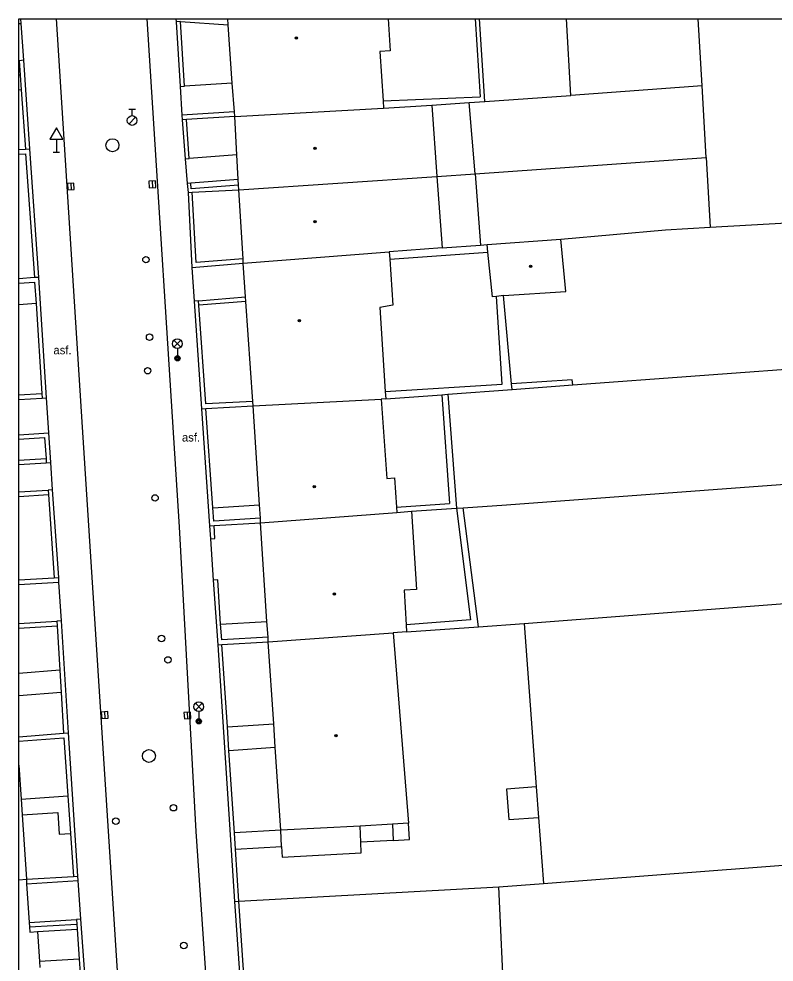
# Model space of a CAD drawing. Extents: x -596024 to -594475, y -1163820 to -1161957.
# Drawn here: x -596024.4 to -595966.1, y -1162029.7 to -1161956.9 of the extents above; entities that cross this region are included whole.
import ezdxf

# ---------------------------------------------------------------- set-up
doc = ezdxf.new("R2010")
doc.units = 0
for name, color, linetype in [('Level 10', 7, 'Continuous'), ('Level 11', 7, 'Continuous'), ('Level 27', 7, 'Continuous'), ('Level 28', 7, 'Continuous'), ('Level 33', 7, 'Continuous'), ('Level 34', 7, 'Continuous'), ('Level 39', 7, 'Continuous'), ('Level 40', 7, 'Continuous'), ('Level 5', 7, 'Continuous'), ('Level 7', 7, 'Continuous'), ('Level 8', 7, 'Continuous'), ('Vrstva 63', 7, 'Continuous')]:
    doc.layers.add(name, color=color, linetype=linetype)

msp = doc.modelspace()

# ---------------------------------------------------------------- linework, layer by layer
at = {"layer": 'Level 10'}
for points in [[(-596021.533, -1161956.88), (-596019.52, -1161988.41), (-596013.74, -1162078.43)], [(-596014.537, -1161956.88), (-596012.03, -1161996.13), (-596010.74, -1162019.65), (-596006.59, -1162080.3)]]:
    msp.add_lwpolyline(points, dxfattribs=at)
at = {"layer": 'Level 11'}
for p, q in [((-596024.42, -1161956.904), (-596024.26, -1161956.89)), ((-595989.166, -1161956.88), (-595988.78, -1161962.9)), ((-595988.41, -1161963.27), (-595988.833, -1161956.88)), ((-595981.78, -1161962.79), (-595982.099, -1161956.88)), ((-595971.64, -1161962.05), (-595971.936, -1161956.88)), ((-596024.31, -1161961.22), (-596024.42, -1161961.227)), ((-596024.23, -1161962.37), (-596024.42, -1161962.383)), ((-596023.09, -1161978.88), (-596024.42, -1161978.965)), ((-596024.42, -1161985.925), (-596022.65, -1161985.82)), ((-596024.42, -1161986.279), (-596022.63, -1161986.17)), ((-596024.42, -1161990.958), (-596022.32, -1161990.83)), ((-596024.42, -1161991.31), (-596022.3, -1161991.18)), ((-596024.42, -1161993.424), (-596022.15, -1161993.28)), ((-596024.42, -1161993.775), (-596022.13, -1161993.63)), ((-596024.42, -1162003.587), (-596021.48, -1162003.41)), ((-596024.42, -1162003.938), (-596021.46, -1162003.76)), ((-596021.25, -1162007.19), (-596024.42, -1162007.443)), ((-596021.15, -1162008.91), (-596024.42, -1162009.172))]:
    msp.add_line(p, q, dxfattribs=at)
for points in [[(-596011.93, -1161957.08), (-596008.25, -1161957.33)], [(-596007.93, -1161961.85), (-596011.62, -1161962.09)], [(-595971.64, -1161962.05), (-595981.78, -1161962.79)], [(-595971.32, -1161967.6), (-595971.64, -1161962.05)], [(-595988.41, -1161963.27), (-595981.78, -1161962.79)], [(-595996.28, -1161963.22), (-595988.78, -1161962.9)], [(-595992.51, -1161963.54), (-595989.62, -1161963.35)], [(-595989.62, -1161963.35), (-595988.41, -1161963.27)], [(-595989.18, -1161968.84), (-595989.62, -1161963.35)], [(-596011.46, -1161964.66), (-596011.81, -1161964.68)], [(-596007.74, -1161964.42), (-596011.46, -1161964.66)], [(-596007.58, -1161967.38), (-596011.26, -1161967.67)], [(-595989.18, -1161968.84), (-595971.32, -1161967.6)], [(-595971.32, -1161967.6), (-595971, -1161972.98)], [(-596007.47, -1161969.28), (-596011.13, -1161969.57)], [(-595992.12, -1161969.05), (-595989.18, -1161968.84)], [(-595989.18, -1161968.84), (-595988.75, -1161974.35)], [(-595982.54, -1161973.89), (-595974.46, -1161973.18), (-595971, -1161972.98)], [(-595971, -1161972.98), (-595963.26, -1161972.54)], [(-595991.71, -1161974.56), (-595988.75, -1161974.35)], [(-595988.75, -1161974.35), (-595988.23, -1161974.31)], [(-595995.76, -1161975.43), (-595988.18, -1161974.9)], [(-596010.53, -1161978.66), (-596006.9, -1161978.36)], [(-596006.88, -1161978.71), (-596010.51, -1161979)], [(-595987.08, -1161985.1), (-595987.53, -1161978.32)], [(-595986.36, -1161985.06), (-595986.98, -1161978.25)], [(-595981.62, -1161985.16), (-595962.01, -1161983.7)], [(-595996.12, -1161985.67), (-595987.08, -1161985.1)], [(-595981.62, -1161985.16), (-595981.68, -1161984.77), (-595986.36, -1161985.06)], [(-595986.32, -1161985.51), (-595986.36, -1161985.06)], [(-595986.32, -1161985.51), (-595981.62, -1161985.16)], [(-595996.08, -1161986.24), (-595991.74, -1161985.91)], [(-595991.74, -1161985.91), (-595991.29, -1161985.88)], [(-595991.74, -1161985.91), (-595991.14, -1161994.32)], [(-595991.29, -1161985.88), (-595986.32, -1161985.51)], [(-595991.29, -1161985.88), (-595990.62, -1161994.67)], [(-595990.1, -1161994.64), (-595986.75, -1161994.42), (-595963.48, -1161992.7), (-595961.5, -1161992.68)], [(-596009.43, -1161994.64), (-596005.83, -1161994.43)], [(-595995.24, -1161994.59), (-595991.14, -1161994.32)], [(-595994.09, -1161994.9), (-595990.62, -1161994.67)], [(-595990.62, -1161994.67), (-595990.1, -1161994.64)], [(-595990.62, -1161994.67), (-595989.52, -1162003.31)], [(-595988.9, -1162003.85), (-595990.1, -1161994.64)], [(-595985.37, -1162003.59), (-595960.87, -1162001.71)], [(-596008.83, -1162003.63), (-596005.25, -1162003.43)], [(-595989.52, -1162003.31), (-595994.51, -1162003.68)], [(-595988.9, -1162003.85), (-595985.37, -1162003.59)], [(-595985.37, -1162003.59), (-595984.45, -1162016.21), (-595984.27, -1162018.56), (-595983.9, -1162023.67)], [(-595994.48, -1162004.24), (-595988.9, -1162003.85)], [(-596008.31, -1162011.57), (-596004.73, -1162011.33)], [(-596008.19, -1162013.39), (-596004.61, -1162013.15)], [(-595984.45, -1162016.21), (-595986.74, -1162016.38), (-595986.57, -1162018.73), (-595984.27, -1162018.56)], [(-596024.25, -1162017.15), (-596020.63, -1162016.91)], [(-596024.17, -1162018.37), (-596021.41, -1162018.18), (-596021.3, -1162019.87), (-596020.44, -1162019.81)], [(-596004.18, -1162019.56), (-596007.77, -1162019.75)], [(-596004.12, -1162020.82), (-596004.18, -1162019.56)], [(-595997.99, -1162020.47), (-595998.04, -1162019.23)], [(-595995.56, -1162019.09), (-595995.5, -1162020.34)], [(-595994.23, -1162020.27), (-595994.33, -1162019.02)], [(-595995.5, -1162020.34), (-595997.99, -1162020.47)], [(-595995.5, -1162020.34), (-595994.23, -1162020.27)], [(-596007.69, -1162021.01), (-596004.12, -1162020.82)], [(-596004.12, -1162020.82), (-596004.09, -1162021.63), (-595997.97, -1162021.3), (-595997.99, -1162020.47)], [(-595983.9, -1162023.67), (-595959.3, -1162021.8)], [(-596007.43, -1162025.03), (-595987.33, -1162023.94)], [(-595987.33, -1162023.94), (-595983.9, -1162023.67)], [(-595975.15, -1162074.45), (-595982.26, -1162075.51), (-595984.48, -1162042.85), (-595986.46, -1162042.87), (-595987.33, -1162023.94)], [(-596007.77, -1162025.05), (-596007.43, -1162025.03)], [(-596023.62, -1162026.68), (-596019.98, -1162026.46)], [(-596023.6, -1162027.03), (-596019.95, -1162026.81)], [(-596022.98, -1162027.39), (-596019.92, -1162027.21)], [(-596019.76, -1162029.51), (-596022.83, -1162029.69)]]:
    msp.add_lwpolyline(points, dxfattribs=at)
at = {"layer": 'Level 27'}
for p, q in [((-596014.125, -1161969.41), (-596014.095, -1161969.909)), ((-596020.415, -1161969.58), (-596020.385, -1161970.08)), ((-596017.807, -1162010.411), (-596017.773, -1162010.909)), ((-596011.417, -1162010.441), (-596011.383, -1162010.939))]:
    msp.add_line(p, q, dxfattribs=at)
for points in [[(-596014.375, -1161969.426), (-596014.344, -1161969.925), (-596013.845, -1161969.894), (-596013.876, -1161969.395)], [(-596020.665, -1161969.596), (-596020.634, -1161970.095), (-596020.135, -1161970.064), (-596020.166, -1161969.565)], [(-596018.057, -1162010.428), (-596018.022, -1162010.927), (-596017.523, -1162010.892), (-596017.558, -1162010.393)], [(-596011.667, -1162010.458), (-596011.632, -1162010.957), (-596011.133, -1162010.922), (-596011.168, -1162010.423)]]:
    msp.add_lwpolyline(points, close=True, dxfattribs=at)
for centre in [(-596017.19, -1161966.64), (-596014.37, -1162013.82)]:
    msp.add_circle(centre, 0.5, dxfattribs=at)
at = {"layer": 'Level 28'}
for p, q in [((-596015.92, -1161963.855), (-596015.42, -1161963.855)), ((-596015.67, -1161964.355), (-596015.67, -1161963.855)), ((-596015.928, -1161965.002), (-596015.398, -1161964.472))]:
    msp.add_line(p, q, dxfattribs=at)
for centre, radius in [((-596015.67, -1161964.73), 0.375), ((-596014.6, -1161975.48), 0.25), ((-596014.32, -1161981.47), 0.25), ((-596014.47, -1161984.06), 0.25), ((-596013.9, -1161993.89), 0.25), ((-596013.4, -1162004.74), 0.25), ((-596012.9, -1162006.4), 0.25), ((-596012.48, -1162017.82), 0.25), ((-596016.93, -1162018.86), 0.25), ((-596011.68, -1162028.46), 0.25)]:
    msp.add_circle(centre, radius, dxfattribs=at)
at = {"layer": 'Level 33'}
for p, q in [((-596012.435, -1161982.24), (-596011.905, -1161981.71)), ((-596012.435, -1161981.71), (-596011.905, -1161982.24)), ((-596012.17, -1161982.35), (-596012.17, -1161983.1)), ((-596010.785, -1162010.28), (-596010.255, -1162009.75)), ((-596010.785, -1162009.75), (-596010.255, -1162010.28)), ((-596010.52, -1162010.39), (-596010.52, -1162011.14))]:
    msp.add_line(p, q, dxfattribs=at)
for centre, radius in [((-596012.17, -1161981.975), 0.375), ((-596012.17, -1161983.1), 0.2), ((-596012.17, -1161983.1), 0.145), ((-596012.17, -1161983.1), 0.0876), ((-596010.52, -1162010.015), 0.375), ((-596010.52, -1162011.14), 0.2), ((-596010.52, -1162011.14), 0.145), ((-596010.52, -1162011.14), 0.0876)]:
    msp.add_circle(centre, radius, dxfattribs=at)
at = {"layer": 'Level 34'}
for p, q in [((-596021.52, -1161966.162), (-596021.52, -1161967.18)), ((-596021.77, -1161967.18), (-596021.27, -1161967.18))]:
    msp.add_line(p, q, dxfattribs=at)
msp.add_lwpolyline([(-596022.02, -1161966.162), (-596021.02, -1161966.162), (-596021.52, -1161965.296)], close=True, dxfattribs=at)
at = {"layer": 'Level 39'}
for centre, radius in [((-596002.98, -1161958.35), 0.09), ((-596002.98, -1161958.35), 0.0398), ((-596001.54, -1161966.89), 0.09), ((-596001.54, -1161966.89), 0.0398), ((-596001.54, -1161972.55), 0.09), ((-596001.54, -1161972.55), 0.0398), ((-595984.89, -1161976), 0.09), ((-595984.89, -1161976), 0.0398), ((-596002.74, -1161980.19), 0.09), ((-596002.74, -1161980.19), 0.0398), ((-596001.6, -1161993.01), 0.09), ((-596001.6, -1161993.01), 0.0398), ((-596000.04, -1162001.31), 0.09), ((-596000.04, -1162001.31), 0.0398), ((-595999.92, -1162012.26), 0.09), ((-595999.92, -1162012.26), 0.0398)]:
    msp.add_circle(centre, radius, dxfattribs=at)
at = {"layer": 'Level 5'}
for p, q in [((-595995.896, -1161956.88), (-595995.73, -1161959.35)), ((-596024.42, -1162023.375), (-596023.84, -1162023.34))]:
    msp.add_line(p, q, dxfattribs=at)
for points in [[(-596007.93, -1161961.85), (-596008.25, -1161957.33), (-596008.282, -1161956.88)], [(-595995.73, -1161959.35), (-595996.54, -1161959.4)], [(-595996.54, -1161959.4), (-595996.28, -1161963.22)], [(-596007.77, -1161964.07), (-596007.93, -1161961.85)], [(-595996.28, -1161963.22), (-595996.24, -1161963.77)], [(-595996.24, -1161963.77), (-595992.51, -1161963.54)], [(-595992.51, -1161963.54), (-595992.12, -1161969.05)], [(-596007.74, -1161964.42), (-596007.77, -1161964.07)], [(-596007.74, -1161964.42), (-595996.24, -1161963.77)], [(-596007.58, -1161967.38), (-596007.74, -1161964.42)], [(-596007.47, -1161969.28), (-596007.58, -1161967.38)], [(-596007.45, -1161969.73), (-596007.47, -1161969.28)], [(-596007.43, -1161970.08), (-595992.12, -1161969.05)], [(-595992.12, -1161969.05), (-595991.71, -1161974.56)], [(-596007.43, -1161970.08), (-596007.45, -1161969.73)], [(-596007.1, -1161975.42), (-596007.43, -1161970.08)], [(-595988.23, -1161974.31), (-595982.54, -1161973.89)], [(-595988.18, -1161974.9), (-595988.23, -1161974.31)], [(-595982.16, -1161977.95), (-595982.54, -1161973.89)], [(-596007.08, -1161975.76), (-595995.8, -1161974.87)], [(-595991.71, -1161974.56), (-595995.8, -1161974.87)], [(-595995.8, -1161974.87), (-595995.76, -1161975.43)], [(-595987.84, -1161978.34), (-595988.18, -1161974.9)], [(-596007.08, -1161975.76), (-596007.1, -1161975.42)], [(-596006.9, -1161978.36), (-596007.08, -1161975.76)], [(-595995.76, -1161975.43), (-595995.52, -1161978.99)], [(-595986.98, -1161978.25), (-595982.16, -1161977.95)], [(-596006.88, -1161978.71), (-596006.9, -1161978.36)], [(-596006.34, -1161986.44), (-596006.88, -1161978.71)], [(-595987.53, -1161978.32), (-595987.84, -1161978.34)], [(-595986.98, -1161978.25), (-595987.53, -1161978.32)], [(-595995.52, -1161978.99), (-595996.52, -1161979.18)], [(-595996.52, -1161979.18), (-595996.12, -1161985.67)], [(-595996.12, -1161985.67), (-595996.08, -1161986.24)], [(-596006.32, -1161986.78), (-596006.34, -1161986.44)], [(-596006.32, -1161986.78), (-595996.44, -1161986.26)], [(-596005.76, -1161995.46), (-596005.83, -1161994.43), (-596006.32, -1161986.78)], [(-595996.08, -1161986.24), (-595996.44, -1161986.26)], [(-595996.44, -1161986.26), (-595995.98, -1161992.38)], [(-595995.98, -1161992.38), (-595995.41, -1161992.34)], [(-595995.41, -1161992.34), (-595995.24, -1161994.59)], [(-595995.24, -1161994.59), (-595995.21, -1161995.02)], [(-595995.21, -1161995.02), (-595994.09, -1161994.9)], [(-595994.09, -1161994.9), (-595993.7, -1162000.97)], [(-596005.74, -1161995.81), (-596005.76, -1161995.46)], [(-596005.74, -1161995.81), (-595995.21, -1161995.02)], [(-596005.17, -1162004.65), (-596005.25, -1162003.43), (-596005.74, -1161995.81)], [(-595993.7, -1162000.97), (-595994.66, -1162001.02)], [(-595994.66, -1162001.02), (-595994.51, -1162003.68)], [(-596005.15, -1162005), (-595995.49, -1162004.32)], [(-595994.48, -1162004.24), (-595995.49, -1162004.32)], [(-595995.49, -1162004.32), (-595994.33, -1162019.02)], [(-595994.51, -1162003.68), (-595994.48, -1162004.24)], [(-596005.15, -1162005), (-596005.17, -1162004.65)], [(-596004.18, -1162019.56), (-596004.61, -1162013.15), (-596004.73, -1162011.33), (-596005.15, -1162005)], [(-596024.42, -1162014.536), (-596024.25, -1162017.15), (-596024.17, -1162018.37), (-596023.84, -1162023.34)], [(-595998.04, -1162019.23), (-596004.18, -1162019.56)], [(-595995.56, -1162019.09), (-595998.04, -1162019.23)], [(-595994.33, -1162019.02), (-595995.56, -1162019.09)], [(-596023.84, -1162023.34), (-596023.82, -1162023.69)], [(-596023.82, -1162023.69), (-596023.62, -1162026.68)], [(-596023.62, -1162026.68), (-596023.6, -1162027.03)], [(-596023.6, -1162027.03), (-596023.58, -1162027.43)], [(-596023.58, -1162027.43), (-596022.98, -1162027.39)], [(-596022.98, -1162027.39), (-596022.83, -1162029.69), (-596022.8, -1162030.16)]]:
    msp.add_lwpolyline(points, dxfattribs=at)
at = {"layer": 'Level 7'}
for p, q in [((-596024.26, -1161956.89), (-596024.261, -1161956.88)), ((-596024.42, -1161957.243), (-596024.24, -1161957.23)), ((-596024.42, -1161966.972), (-596023.92, -1161966.94)), ((-596024.42, -1161967.332), (-596023.9, -1161967.3)), ((-596023.22, -1161976.87), (-596024.42, -1161976.952)), ((-596024.42, -1161977.307), (-596023.2, -1161977.23)), ((-596024.42, -1161989.007), (-596022.11, -1161988.86)), ((-596024.42, -1162000.214), (-596021.69, -1162000.05)), ((-596024.42, -1162000.575), (-596021.32, -1162000.39)), ((-596024.42, -1162012.329), (-596020.96, -1162012.05)), ((-596024.42, -1162012.681), (-596020.94, -1162012.42))]:
    msp.add_line(p, q, dxfattribs=at)
for points in [[(-596024.24, -1161957.23), (-596024.26, -1161956.89)], [(-596011.62, -1161962.09), (-596011.93, -1161957.08), (-596012.28, -1161957.1)], [(-596012.28, -1161957.1), (-596011.97, -1161962.11)], [(-596024.04, -1161960.08), (-596024.39, -1161960.11), (-596024.31, -1161961.22), (-596024.23, -1161962.37), (-596023.92, -1161966.94)], [(-596023.58, -1161966.92), (-596024.04, -1161960.08)], [(-596011.97, -1161962.11), (-596011.62, -1161962.09)], [(-596007.77, -1161964.07), (-596011.83, -1161964.33)], [(-596011.83, -1161964.33), (-596011.81, -1161964.68)], [(-596011.81, -1161964.68), (-596011.56, -1161967.69)], [(-596011.26, -1161967.67), (-596011.46, -1161964.66)], [(-596023.92, -1161966.94), (-596023.58, -1161966.92)], [(-596022.87, -1161976.85), (-596023.58, -1161966.92)], [(-596023.9, -1161967.3), (-596023.22, -1161976.87)], [(-596011.56, -1161967.69), (-596011.26, -1161967.67)], [(-596011.13, -1161969.57), (-596011.41, -1161969.59)], [(-596011.41, -1161969.59), (-596011.35, -1161970.28)], [(-596011.1, -1161970.02), (-596011.13, -1161969.57)], [(-596007.45, -1161969.73), (-596011.1, -1161970.02)], [(-596011.03, -1161970.26), (-596007.43, -1161970.08)], [(-596011.35, -1161970.28), (-596011.03, -1161970.26)], [(-596011.35, -1161970.28), (-596011.05, -1161976.08)], [(-596010.73, -1161975.71), (-596011.03, -1161970.26)], [(-596011.05, -1161976.08), (-596007.08, -1161975.76)], [(-596007.1, -1161975.42), (-596010.73, -1161975.71)], [(-596022.87, -1161976.85), (-596023.22, -1161976.87)], [(-596023.2, -1161977.23), (-596023.09, -1161978.88), (-596022.65, -1161985.82)], [(-596022.28, -1161986.15), (-596022.87, -1161976.85)], [(-596010.53, -1161978.66), (-596010.87, -1161978.68)], [(-596010.87, -1161978.68), (-596010.31, -1161987)], [(-596010.51, -1161979), (-596010.53, -1161978.66)], [(-596009.98, -1161986.63), (-596010.51, -1161979)], [(-596022.65, -1161985.82), (-596022.63, -1161986.17)], [(-596022.63, -1161986.17), (-596022.28, -1161986.15)], [(-596006.34, -1161986.44), (-596009.98, -1161986.63)], [(-596009.97, -1161986.98), (-596006.32, -1161986.78)], [(-596010.31, -1161987), (-596009.97, -1161986.98)], [(-596010.31, -1161987), (-596009.69, -1161996.04)], [(-596009.36, -1161995.67), (-596009.43, -1161994.64), (-596009.97, -1161986.98)], [(-596021.95, -1161991.16), (-596022.11, -1161988.86)], [(-596024.42, -1161989.352), (-596022.43, -1161989.23), (-596022.32, -1161990.83)], [(-596022.32, -1161990.83), (-596022.3, -1161991.18)], [(-596022.3, -1161991.18), (-596021.95, -1161991.16)], [(-596021.81, -1161993.26), (-596022.15, -1161993.28)], [(-596022.15, -1161993.28), (-596022.13, -1161993.63)], [(-596021.34, -1162000.03), (-596021.81, -1161993.26)], [(-596022.13, -1161993.63), (-596021.69, -1162000.05)], [(-596005.76, -1161995.46), (-596009.36, -1161995.67)], [(-596009.69, -1161996.04), (-596009.34, -1161996.02)], [(-596009.69, -1161996.04), (-596009.62, -1161997.04)], [(-596009.62, -1161997.04), (-596009.27, -1161997.01), (-596009.34, -1161996.02)], [(-596009.34, -1161996.02), (-596005.74, -1161995.81)], [(-596021.69, -1162000.05), (-596021.34, -1162000.03)], [(-596021.32, -1162000.39), (-596021.34, -1162000.03)], [(-596008.75, -1162004.85), (-596008.83, -1162003.63), (-596009.06, -1162000.21), (-596009.4, -1162000.23)], [(-596009.4, -1162000.23), (-596009.06, -1162005.24)], [(-596021.13, -1162003.39), (-596021.48, -1162003.41)], [(-596021.48, -1162003.41), (-596021.46, -1162003.76)], [(-596020.58, -1162012.02), (-596021.13, -1162003.39)], [(-596021.46, -1162003.76), (-596021.25, -1162007.19), (-596021.15, -1162008.91), (-596020.96, -1162012.05)], [(-596005.17, -1162004.65), (-596008.75, -1162004.85)], [(-596008.73, -1162005.22), (-596005.15, -1162005)], [(-596009.06, -1162005.24), (-596008.73, -1162005.22)], [(-596009.06, -1162005.24), (-596007.77, -1162025.05)], [(-596007.77, -1162019.75), (-596008.19, -1162013.39), (-596008.31, -1162011.57), (-596008.73, -1162005.22)], [(-596020.96, -1162012.05), (-596020.58, -1162012.02)], [(-596019.86, -1162023.1), (-596020.58, -1162012.02)], [(-596020.94, -1162012.42), (-596020.63, -1162016.91), (-596020.44, -1162019.81), (-596020.21, -1162023.12)], [(-596007.69, -1162021.01), (-596007.77, -1162019.75)], [(-596007.43, -1162025.03), (-596007.69, -1162021.01)], [(-596023.84, -1162023.34), (-596020.21, -1162023.12)], [(-596020.21, -1162023.12), (-596019.86, -1162023.1)], [(-596019.84, -1162023.44), (-596019.86, -1162023.1)], [(-596023.82, -1162023.69), (-596019.84, -1162023.44)], [(-596007.77, -1162025.05), (-596006.16, -1162047.82)], [(-596006.16, -1162047.82), (-596005.89, -1162047.8), (-596007.43, -1162025.03)], [(-596019.62, -1162026.43), (-596019.98, -1162026.46)], [(-596019.98, -1162026.46), (-596019.95, -1162026.81)], [(-596019.95, -1162026.81), (-596019.92, -1162027.21), (-596019.76, -1162029.51), (-596019.42, -1162034.19)], [(-596019.07, -1162034.17), (-596019.62, -1162026.43)]]:
    msp.add_lwpolyline(points, dxfattribs=at)
at = {"layer": 'Level 8'}
msp.add_line((-596012.294, -1161956.88), (-596012.28, -1161957.1), dxfattribs=at)
for points in [[(-596024.04, -1161960.08), (-596024.24, -1161957.23)], [(-596011.97, -1161962.11), (-596011.83, -1161964.33)], [(-596011.56, -1161967.69), (-596011.41, -1161969.59)], [(-596011.05, -1161976.08), (-596010.87, -1161978.68)], [(-596022.11, -1161988.86), (-596022.28, -1161986.15)], [(-596021.81, -1161993.26), (-596021.95, -1161991.16)], [(-596009.62, -1161997.04), (-596009.4, -1162000.23)], [(-596021.13, -1162003.39), (-596021.32, -1162000.39)], [(-596019.62, -1162026.43), (-596019.84, -1162023.44)]]:
    msp.add_lwpolyline(points, dxfattribs=at)
at = {"layer": 'Vrstva 63'}
msp.add_lwpolyline([(-594475.47, -1163820.23), (-596024.42, -1163820.23), (-596024.42, -1161956.88), (-594475.47, -1161956.88)], close=True, dxfattribs=at)

# ---------------------------------------------------------------- texts
at = {"layer": 'Level 40'}
for p in [(-596021.75, -1161982.79), (-596011.82, -1161989.53)]:
    msp.add_text('asf.', height=0.65, dxfattribs=at).set_placement(p)

doc.saveas('drawing.dxf')
